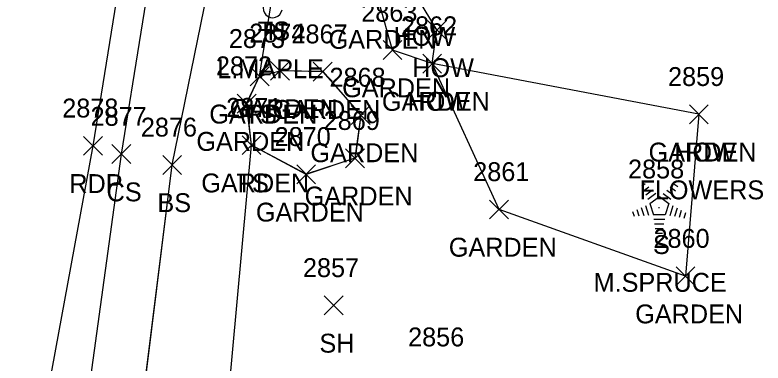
# Model space of a CAD drawing. Extents: x 1554668 to 1563881, y 831386 to 834374.
# Drawn here: x 1562274.2 to 1562353.5, y 832725.5 to 832762.4 of the extents above; entities that cross this region are included whole.
import ezdxf

# ---------------------------------------------------------------- set-up
doc = ezdxf.new("R2010")
doc.units = 0
for name, color, linetype in [('L_A', 7, 'Continuous'), ('L_C', 7, 'Continuous'), ('L_I', 7, 'Continuous'), ('L_TIC', 7, 'Continuous'), ('LAPB', 7, 'Continuous'), ('LBC', 7, 'Continuous'), ('LELB', 7, 'Continuous'), ('LTC', 7, 'Continuous'), ('LTD', 7, 'Continuous'), ('P_A', 7, 'Continuous'), ('P_I', 7, 'Continuous'), ('P_TIC', 7, 'Continuous'), ('PET', 7, 'Continuous')]:
    doc.layers.add(name, color=color, linetype=linetype)

msp = doc.modelspace()

# ---------------------------------------------------------------- linework, layer by layer
at = {"layer": 'L_TIC'}
for points in [[(1562317.919, 832759.779), (1562319.919, 832761.779)], [(1562319.919, 832759.779), (1562317.919, 832761.779)], [(1562313.198, 832757.651), (1562315.198, 832759.651)], [(1562315.198, 832757.651), (1562313.198, 832759.651)], [(1562317.413, 832756.216), (1562319.413, 832758.216)], [(1562319.413, 832756.216), (1562317.413, 832758.216)], [(1562317.413, 832756.216), (1562319.413, 832758.216)], [(1562319.413, 832756.216), (1562317.413, 832758.216)], [(1562301.28, 832755.445), (1562303.28, 832757.445)], [(1562303.28, 832755.445), (1562301.28, 832757.445)], [(1562301.28, 832755.445), (1562303.28, 832757.445)], [(1562303.28, 832755.445), (1562301.28, 832757.445)], [(1562305.803, 832755.358), (1562307.803, 832757.358)], [(1562307.803, 832755.358), (1562305.803, 832757.358)], [(1562305.803, 832755.358), (1562307.803, 832757.358)], [(1562307.803, 832755.358), (1562305.803, 832757.358)], [(1562299.118, 832754.868), (1562301.118, 832756.868)], [(1562301.118, 832754.868), (1562299.118, 832756.868)], [(1562299.118, 832754.868), (1562301.118, 832756.868)], [(1562301.118, 832754.868), (1562299.118, 832756.868)], [(1562297.746, 832751.975), (1562299.746, 832753.975)], [(1562299.746, 832751.975), (1562297.746, 832753.975)], [(1562309.835, 832750.772), (1562311.835, 832752.772)], [(1562311.835, 832750.772), (1562309.835, 832752.772)], [(1562345.678, 832750.843), (1562347.678, 832752.843)], [(1562347.678, 832750.843), (1562345.678, 832752.843)], [(1562345.678, 832750.843), (1562347.678, 832752.843)], [(1562347.678, 832750.843), (1562345.678, 832752.843)], [(1562298.266, 832747.574), (1562300.266, 832749.574)], [(1562300.266, 832747.574), (1562298.266, 832749.574)], [(1562298.266, 832747.574), (1562300.266, 832749.574)], [(1562300.266, 832747.574), (1562298.266, 832749.574)], [(1562284.462, 832746.629), (1562286.462, 832748.629)], [(1562286.462, 832746.629), (1562284.462, 832748.629)], [(1562309.225, 832746.189), (1562311.225, 832748.189)], [(1562311.225, 832746.189), (1562309.225, 832748.189)], [(1562289.845, 832745.485), (1562291.845, 832747.485)], [(1562291.845, 832745.485), (1562289.845, 832747.485)], [(1562304.056, 832744.486), (1562306.056, 832746.486)], [(1562306.056, 832744.486), (1562304.056, 832746.486)], [(1562324.502, 832740.769), (1562326.502, 832742.769)], [(1562326.502, 832740.769), (1562324.502, 832742.769)], [(1562344.262, 832733.703), (1562346.262, 832735.703)], [(1562346.262, 832733.703), (1562344.262, 832735.703)], [(1562306.973, 832730.604), (1562308.973, 832732.604)], [(1562308.973, 832730.604), (1562306.973, 832732.604)]]:
    msp.add_lwpolyline(points, dxfattribs=at)
at = {"layer": 'LAPB'}
for points in [[(1562346.678, 832751.843), (1562345.262, 832734.703), (1562325.502, 832741.769), (1562318.413, 832757.216), (1562314.198, 832758.651), (1562312.763, 832763.782), (1562313.831, 832774.806)], [(1562346.682, 832751.844), (1562345.266, 832734.703), (1562325.504, 832741.767), (1562318.416, 832757.217), (1562314.199, 832758.648), (1562312.767, 832763.783), (1562313.836, 832774.807)], [(1562346.682, 832751.844), (1562345.266, 832734.703), (1562325.504, 832741.767), (1562318.416, 832757.217), (1562314.199, 832758.648), (1562312.767, 832763.783), (1562313.836, 832774.807)], [(1562346.682, 832751.844), (1562345.266, 832734.703), (1562325.504, 832741.767), (1562318.416, 832757.217), (1562314.199, 832758.648), (1562312.767, 832763.783), (1562313.836, 832774.807)], [(1562306.803, 832756.358), (1562310.835, 832751.772), (1562310.225, 832747.189), (1562305.056, 832745.486), (1562299.266, 832748.574), (1562298.746, 832752.975), (1562300.118, 832755.868), (1562302.28, 832756.445)], [(1562306.808, 832756.361), (1562310.837, 832751.77), (1562310.23, 832747.19), (1562305.061, 832745.488), (1562299.269, 832748.573), (1562298.747, 832752.971), (1562300.122, 832755.868), (1562302.281, 832756.441)], [(1562306.808, 832756.361), (1562310.837, 832751.77), (1562310.23, 832747.19), (1562305.061, 832745.488), (1562299.269, 832748.573), (1562298.747, 832752.971), (1562300.122, 832755.868), (1562302.281, 832756.441)], [(1562306.808, 832756.361), (1562310.837, 832751.77), (1562310.23, 832747.19), (1562305.061, 832745.488), (1562299.269, 832748.573), (1562298.747, 832752.971), (1562300.122, 832755.868), (1562302.281, 832756.441)], [(1562306.803, 832756.358), (1562302.28, 832756.445)], [(1562306.808, 832756.361), (1562302.281, 832756.441)], [(1562306.808, 832756.361), (1562302.281, 832756.441)], [(1562306.808, 832756.361), (1562302.281, 832756.441)]]:
    msp.add_lwpolyline(points, dxfattribs=at)
at = {"layer": 'LBC'}
for points in [[(1562346.678, 832751.843), (1562318.413, 832757.216), (1562318.919, 832760.779), (1562316.924, 832764.091), (1562317.644, 832767.661), (1562320.545, 832769.906), (1562321.065, 832772.064), (1562322.717, 832780.79), (1562323.108, 832782.98), (1562321.151, 832786.115), (1562321.739, 832789.892), (1562324.694, 832792.105), (1562325.399, 832795.57), (1562327.681, 832795.313), (1562328.333, 832799.591), (1562330.598, 832799.381), (1562334.543, 832798.596), (1562338.554, 832797.891)], [(1562346.682, 832751.844), (1562318.416, 832757.217), (1562318.921, 832760.776), (1562316.927, 832764.091), (1562317.647, 832767.666), (1562320.548, 832769.91), (1562321.066, 832772.072), (1562322.72, 832780.795), (1562323.111, 832782.984), (1562321.151, 832786.123), (1562321.743, 832789.895), (1562324.698, 832792.108), (1562325.4, 832795.576), (1562327.685, 832795.316), (1562328.337, 832799.593), (1562330.6, 832799.386), (1562334.549, 832798.596), (1562338.56, 832797.892)], [(1562346.682, 832751.844), (1562318.416, 832757.217), (1562318.921, 832760.776), (1562316.927, 832764.091), (1562317.647, 832767.666), (1562320.548, 832769.91), (1562321.066, 832772.072), (1562322.72, 832780.795), (1562323.111, 832782.984), (1562321.151, 832786.123), (1562321.743, 832789.895), (1562324.698, 832792.108), (1562325.4, 832795.576), (1562327.685, 832795.316), (1562328.337, 832799.593), (1562330.6, 832799.386), (1562334.549, 832798.596), (1562338.56, 832797.892)], [(1562346.682, 832751.844), (1562318.416, 832757.217), (1562318.921, 832760.776), (1562316.927, 832764.091), (1562317.647, 832767.666), (1562320.548, 832769.91), (1562321.066, 832772.072), (1562322.72, 832780.795), (1562323.111, 832782.984), (1562321.151, 832786.123), (1562321.743, 832789.895), (1562324.698, 832792.108), (1562325.4, 832795.576), (1562327.685, 832795.316), (1562328.337, 832799.593), (1562330.6, 832799.386), (1562334.549, 832798.596), (1562338.56, 832797.892)]]:
    msp.add_lwpolyline(points, dxfattribs=at)
at = {"layer": 'LELB'}
for points in [[(1562265.098, 832626.674), (1562270.393, 832656.119), (1562275.307, 832678.436), (1562280.771, 832713.502), (1562285.467, 832747.632), (1562291.733, 832786.42), (1562295.546, 832804.187), (1562301.548, 832814.193)], [(1562265.098, 832626.674), (1562270.393, 832656.119), (1562275.307, 832678.436), (1562280.771, 832713.502), (1562285.467, 832747.632), (1562291.733, 832786.42), (1562295.546, 832804.187), (1562301.548, 832814.193)], [(1562265.098, 832626.674), (1562270.393, 832656.119), (1562275.307, 832678.436), (1562280.771, 832713.502), (1562285.467, 832747.632), (1562291.733, 832786.42), (1562295.546, 832804.187), (1562301.548, 832814.193)], [(1562265.099, 832626.673), (1562270.388, 832656.119), (1562275.305, 832678.438), (1562280.768, 832713.503), (1562285.462, 832747.629), (1562291.73, 832786.42), (1562295.544, 832804.181), (1562301.546, 832814.186)], [(1562279.775, 832656.677), (1562276.298, 832659.898), (1562280.445, 832677.477), (1562286.521, 832711.763), (1562290.845, 832746.485), (1562296.936, 832776.259), (1562297.775, 832779.164)], [(1562279.776, 832656.676), (1562276.3, 832659.897), (1562280.448, 832677.476), (1562286.525, 832711.763), (1562290.85, 832746.487), (1562296.939, 832776.259), (1562297.78, 832779.166)], [(1562279.776, 832656.676), (1562276.3, 832659.897), (1562280.448, 832677.476), (1562286.525, 832711.763), (1562290.85, 832746.487), (1562296.939, 832776.259), (1562297.78, 832779.166)], [(1562279.776, 832656.676), (1562276.3, 832659.897), (1562280.448, 832677.476), (1562286.525, 832711.763), (1562290.85, 832746.487), (1562296.939, 832776.259), (1562297.78, 832779.166)], [(1562300.118, 832755.868), (1562301.521, 832764.668), (1562305.356, 832777.78)], [(1562300.122, 832755.868), (1562301.526, 832764.671), (1562305.358, 832777.778)], [(1562300.122, 832755.868), (1562301.526, 832764.671), (1562305.358, 832777.778)], [(1562300.122, 832755.868), (1562301.526, 832764.671), (1562305.358, 832777.778)], [(1562282.332, 832656.045), (1562284.68, 832660.182), (1562288.013, 832675.892), (1562295.711, 832709.979), (1562299.266, 832748.574)], [(1562282.333, 832656.044), (1562284.684, 832660.181), (1562288.016, 832675.892), (1562295.713, 832709.976), (1562299.269, 832748.573)], [(1562282.333, 832656.044), (1562284.684, 832660.181), (1562288.016, 832675.892), (1562295.713, 832709.976), (1562299.269, 832748.573)], [(1562282.333, 832656.044), (1562284.684, 832660.181), (1562288.016, 832675.892), (1562295.713, 832709.976), (1562299.269, 832748.573)]]:
    msp.add_lwpolyline(points, dxfattribs=at)
at = {"layer": 'LTC'}
for p, q in [((1562340.626, 832744.257), (1562340.98, 832744.515)), ((1562340.835, 832743.792), (1562341.365, 832744.176)), ((1562341.045, 832743.326), (1562341.749, 832743.837)), ((1562343.282, 832743.801), (1562343.961, 832743.307)), ((1562343.653, 832744.149), (1562344.202, 832743.75)), ((1562344.024, 832744.498), (1562344.443, 832744.193)), ((1562341.255, 832742.86), (1562342.133, 832743.498)), ((1562341.479, 832742.405), (1562342.491, 832743.14)), ((1562342.491, 832743.14), (1562343.488, 832742.415)), ((1562342.911, 832743.453), (1562343.72, 832742.864)), ((1562341.025, 832742.186), (1562341.355, 832741.167)), ((1562341.479, 832742.405), (1562341.866, 832741.212)), ((1562343.488, 832742.415), (1562343.097, 832741.212)), ((1562343.925, 832742.144), (1562343.587, 832741.104)), ((1562339.658, 832741.536), (1562339.81, 832741.068)), ((1562340.114, 832741.753), (1562340.325, 832741.101)), ((1562340.569, 832741.97), (1562340.84, 832741.134)), ((1562344.37, 832741.893), (1562344.082, 832741.009)), ((1562344.815, 832741.643), (1562344.577, 832740.914)), ((1562345.259, 832741.393), (1562345.072, 832740.819)), ((1562343.097, 832741.212), (1562341.866, 832741.212)), ((1562343.058, 832740.712), (1562341.914, 832740.712)), ((1562342.975, 832740.212), (1562341.986, 832740.212)), ((1562342.891, 832739.712), (1562342.059, 832739.712)), ((1562342.807, 832739.212), (1562342.132, 832739.212))]:
    msp.add_line(p, q, dxfattribs=at)
at = {"layer": 'LTD'}
msp.add_ellipse((1562301.521, 832763.168), major_axis=(0.265, 1.061), ratio=0.942809, start_param=1.570796, end_param=4.712389, dxfattribs=at)
at = {"layer": 'P_TIC'}
for points in [[(1562281.459, 832747.505), (1562283.459, 832749.505)], [(1562283.459, 832747.505), (1562281.459, 832749.505)]]:
    msp.add_lwpolyline(points, dxfattribs=at)
at = {"layer": 'PET'}
for points in [[(1562193.167, 832267.13), (1562201.146, 832309.703), (1562207.218, 832342.575), (1562208.538, 832349.445), (1562211.679, 832366.094), (1562212.836, 832373.113), (1562216.871, 832394.677), (1562221.784, 832421.25), (1562225.693, 832442.111), (1562233.351, 832484.078), (1562234.186, 832488.931), (1562241.957, 832528.547), (1562242.008, 832533.059), (1562244.222, 832536.962), (1562248.062, 832556.9), (1562257.295, 832610.994), (1562261.428, 832631.195), (1562266.166, 832657.988), (1562270.512, 832679.644), (1562276.163, 832714.072), (1562282.459, 832748.505), (1562288.68, 832787.056), (1562293.2, 832810.286), (1562300.396, 832850.568)], [(1562193.171, 832267.13), (1562201.149, 832309.703), (1562207.222, 832342.574), (1562208.542, 832349.444), (1562211.683, 832366.093), (1562212.84, 832373.112), (1562216.874, 832394.674), (1562221.788, 832421.249), (1562225.694, 832442.106), (1562233.354, 832484.072), (1562234.19, 832488.925), (1562241.961, 832528.547), (1562242.013, 832533.06), (1562244.225, 832536.956), (1562248.066, 832556.896), (1562257.301, 832610.991), (1562261.43, 832631.195), (1562266.171, 832657.989), (1562270.514, 832679.643), (1562276.166, 832714.07), (1562282.463, 832748.508), (1562288.682, 832787.054), (1562293.205, 832810.287), (1562300.398, 832850.573)], [(1562193.171, 832267.13), (1562201.149, 832309.703), (1562207.222, 832342.574), (1562208.542, 832349.444), (1562211.683, 832366.093), (1562212.84, 832373.112), (1562216.874, 832394.674), (1562221.788, 832421.249), (1562225.694, 832442.106), (1562233.354, 832484.072), (1562234.19, 832488.925), (1562241.961, 832528.547), (1562242.013, 832533.06), (1562244.225, 832536.956), (1562248.066, 832556.896), (1562257.301, 832610.991), (1562261.43, 832631.195), (1562266.171, 832657.989), (1562270.514, 832679.643), (1562276.166, 832714.07), (1562282.463, 832748.508), (1562288.682, 832787.054), (1562293.205, 832810.287), (1562300.398, 832850.573)], [(1562193.171, 832267.13), (1562201.149, 832309.703), (1562207.222, 832342.574), (1562208.542, 832349.444), (1562211.683, 832366.093), (1562212.84, 832373.112), (1562216.874, 832394.674), (1562221.788, 832421.249), (1562225.694, 832442.106), (1562233.354, 832484.072), (1562234.19, 832488.925), (1562241.961, 832528.547), (1562242.013, 832533.06), (1562244.225, 832536.956), (1562248.066, 832556.896), (1562257.301, 832610.991), (1562261.43, 832631.195), (1562266.171, 832657.989), (1562270.514, 832679.643), (1562276.166, 832714.07), (1562282.463, 832748.508), (1562288.682, 832787.054), (1562293.205, 832810.287), (1562300.398, 832850.573)]]:
    msp.add_lwpolyline(points, dxfattribs=at)

# ---------------------------------------------------------------- texts
at = {"layer": 'L_A'}
for s, p in [('TS', (1562299.93, 832759.668)), ('H', (1562300.954, 832759.668)), ('GARDEN', (1562307.432, 832758.782)), ('HOW', (1562314.31, 832759.091)), ('HOW', (1562316.305, 832755.779)), ('GARDEN', (1562308.867, 832753.651)), ('GARDEN', (1562313.082, 832752.216)), ('HOW', (1562315.798, 832752.216)), ('GARDEN', (1562296.949, 832751.445)), ('GARDEN', (1562296.949, 832751.445)), ('GARDEN', (1562301.472, 832751.358)), ('GARDEN', (1562301.472, 832751.358)), ('GARDEN', (1562294.788, 832750.868)), ('TS', (1562298.528, 832750.868)), ('GARDEN', (1562293.415, 832747.975)), ('GARDEN', (1562305.505, 832746.772)), ('GARDEN', (1562341.347, 832746.843)), ('HOW', (1562344.064, 832746.843)), ('GARDEN', (1562293.935, 832743.574)), ('TS', (1562297.676, 832743.574)), ('CS', (1562283.903, 832742.629)), ('GARDEN', (1562304.895, 832742.189)), ('BS', (1562289.286, 832741.485)), ('GARDEN', (1562299.725, 832740.486)), ('S', (1562341.816, 832737.049)), ('GARDEN', (1562320.172, 832736.769)), ('GARDEN', (1562339.931, 832729.703)), ('SH', (1562306.461, 832726.604))]:
    msp.add_text(s, height=2, dxfattribs=at).set_placement(p)
at = {"layer": 'L_C'}
for s, p in [('L.MAPLE', (1562295.631, 832755.668)), ('FLOWERS', (1562340.379, 832742.843)), ('M.SPRUCE', (1562335.517, 832733.049))]:
    msp.add_text(s, height=2, dxfattribs=at).set_placement(p)
at = {"layer": 'L_I'}
for s, p in [('2863', (1562310.891, 832761.651)), ('2862', (1562315.106, 832760.216)), ('2862', (1562315.106, 832760.216)), ('2874', (1562299.02, 832759.445)), ('2874', (1562299.02, 832759.445)), ('2867', (1562303.496, 832759.358)), ('2867', (1562303.496, 832759.358)), ('2873', (1562296.859, 832758.868)), ('2873', (1562296.859, 832758.868)), ('2872', (1562295.486, 832755.975)), ('2868', (1562307.528, 832754.772)), ('2859', (1562343.41, 832754.843)), ('2859', (1562343.41, 832754.843)), ('2871', (1562296.573, 832751.574)), ('2871', (1562296.573, 832751.574)), ('2877', (1562282.202, 832750.629)), ('2869', (1562306.91, 832750.189)), ('2876', (1562287.53, 832749.485)), ('2870', (1562301.709, 832748.486)), ('2858', (1562339.171, 832745.049)), ('2861', (1562322.762, 832744.769)), ('2860', (1562341.868, 832737.703)), ('2857', (1562304.713, 832734.604)), ('2856', (1562315.858, 832727.266))]:
    msp.add_text(s, height=2, dxfattribs=at).set_placement(p)
at = {"layer": 'LTC'}
msp.add_text('.', height=1.037, rotation=270, dxfattribs=at).set_placement((1562342.373, 832742.153))
at = {"layer": 'P_A'}
msp.add_text('RDP', height=2, dxfattribs=at).set_placement((1562279.947, 832743.505))
at = {"layer": 'P_I'}
msp.add_text('2878', height=2, dxfattribs=at).set_placement((1562279.199, 832751.505))

doc.saveas('drawing.dxf')
